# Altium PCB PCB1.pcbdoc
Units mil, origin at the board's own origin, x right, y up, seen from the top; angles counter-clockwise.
Board outline 1870.1 x 2920.8 mil, 2 copper layers (Top Layer, Bottom Layer), stack 62.2 mil thick; 51 components, 45 nets, 147 pads, 92 vias.
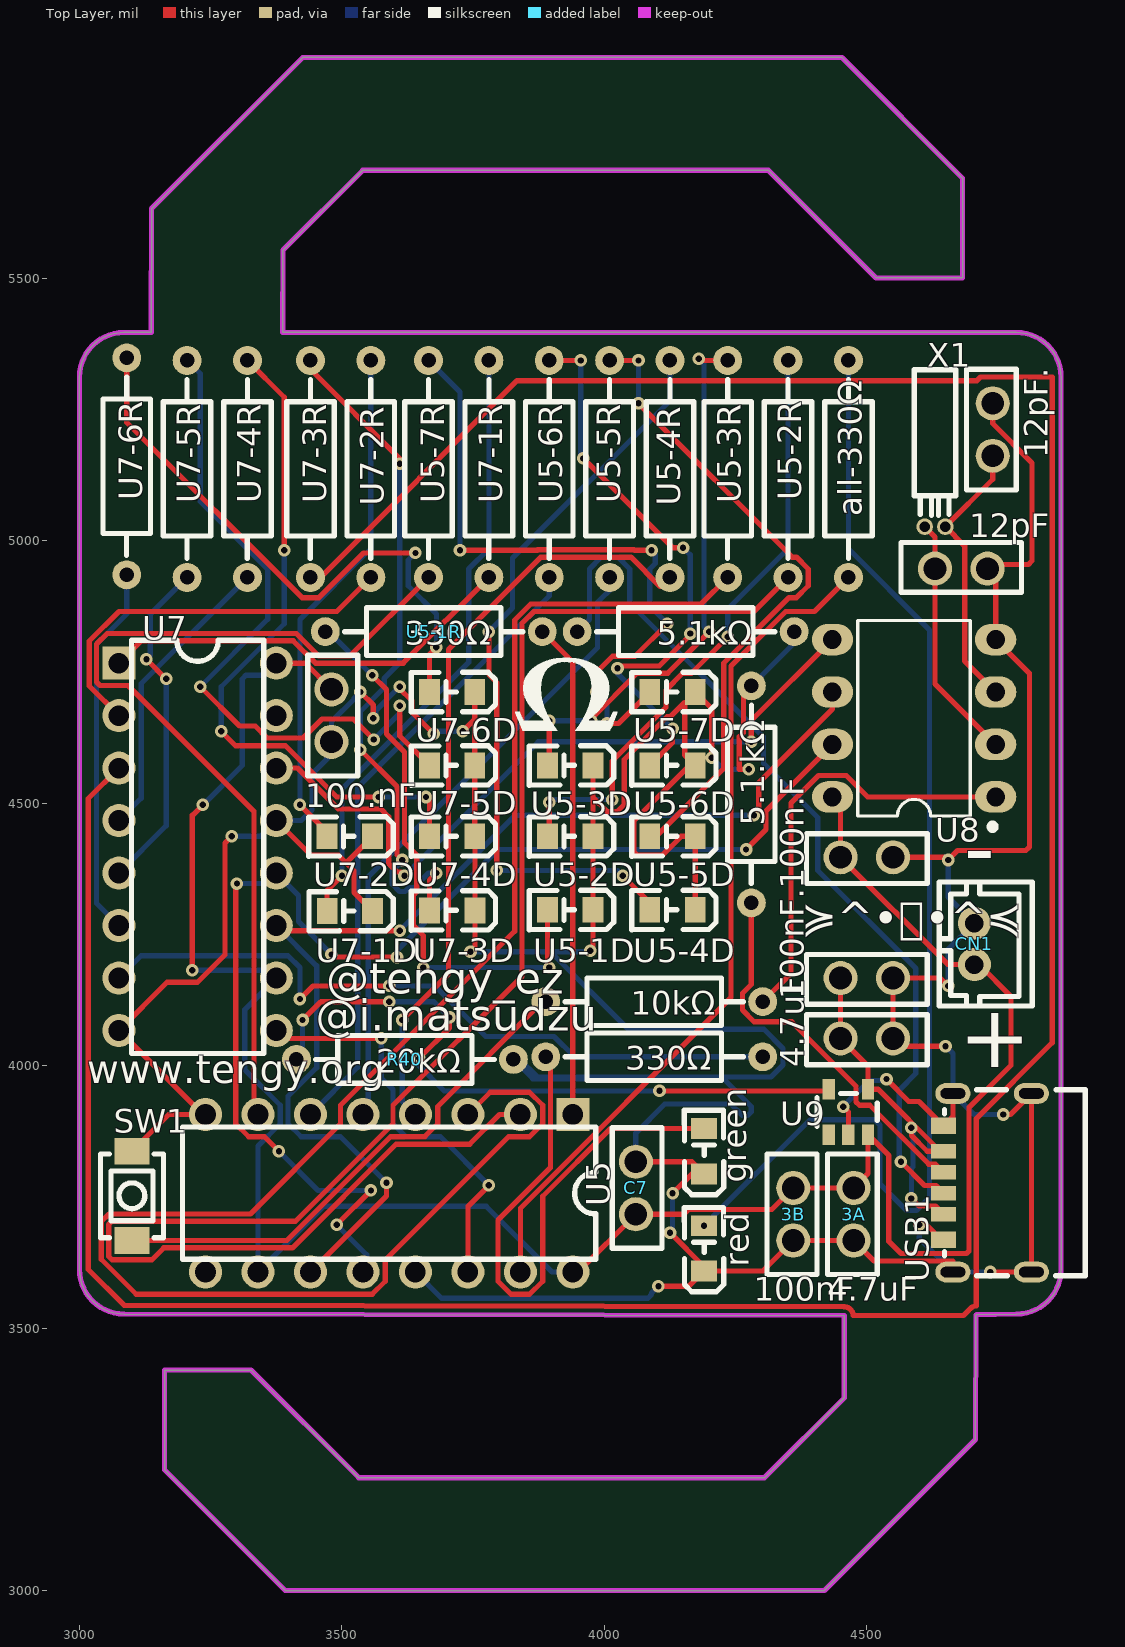
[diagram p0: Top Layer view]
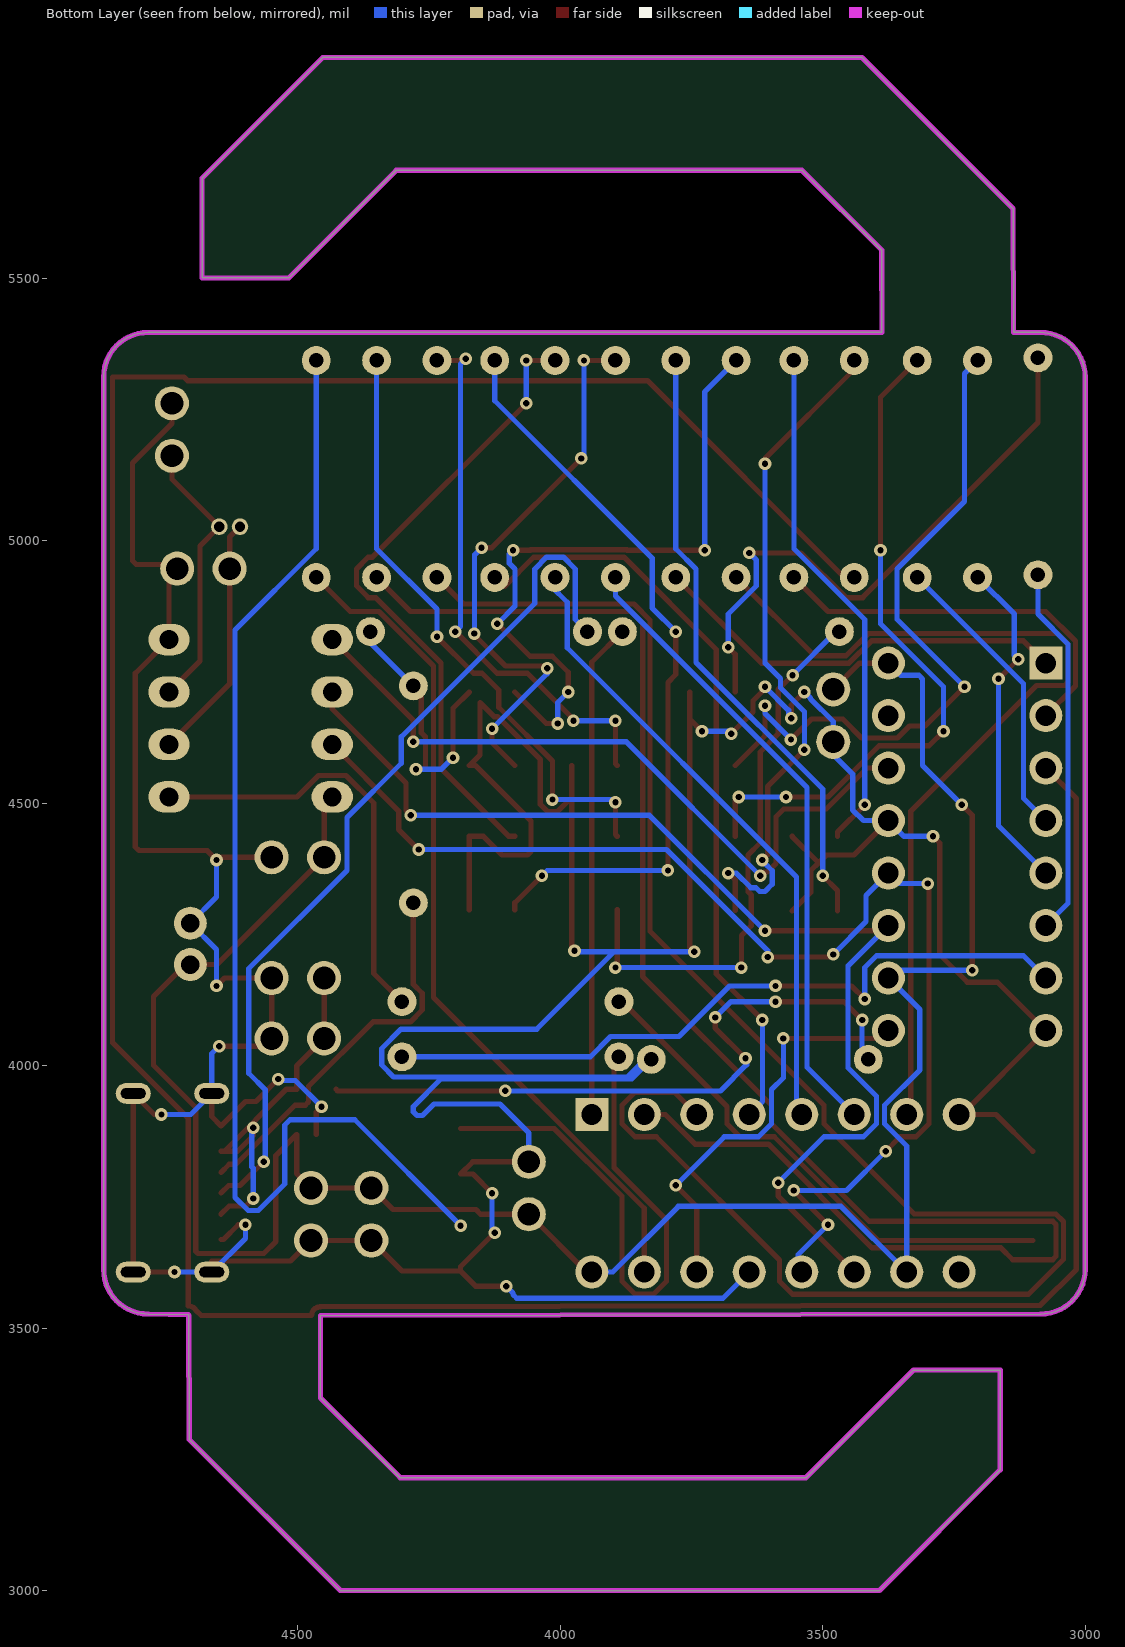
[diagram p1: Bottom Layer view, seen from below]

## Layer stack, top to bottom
Top Solder Mask Layer: solder mask 0.4, Dk 3.3
Top Layer: signal copper 1.4
Dielectric1: surface 59.4, FR4, Dk 4.5
Bottom Layer: signal copper 1.4
Bottom Solder Mask Layer: solder mask 0.4, Dk 3.3

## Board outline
4785.1,3526.8 4709,3525.4 4708,3523.8 4707,3287.9 4419.1,3000 3392,3000 3162,3230 3162,3420 3327,3420 3532,3215 4304.9,3215 4457,3367.1 4457.1,3523.8 3085,3526.8 cw(c3085,3611.8) 3000,3611.8 3000,5311.9 cw(c3085,5311.9) 3085,5396.9 3084.7,5396.9 3136.5,5396.9 3137.4,5632.8 3425.4,5920.8 4452.5,5920.8 4682.5,5690.8 4682.5,5500.8 4517.5,5500.8 4312.5,5705.8 3539.6,5705.8 3387.5,5553.7 3387.3,5396.9 4785.1,5396.9 cw(c4785.1,5311.9) 4870.1,5311.9 4870.1,3611.8 cw(c4785.1,3611.8)

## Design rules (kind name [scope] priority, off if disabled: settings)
BoardOutlineClearance copperThickness1oz [All] p0: genericclearance=10 ignorepadtopadclearanceinfootprint=FALSE except(0: Arc-SplitContinuation Track-SplitContinuation SMDPad-SplitContinuation THPad-SplitContinuation Via-SplitContinuation Fill-SplitContinuation Poly-SplitContinuation Region-SplitContinuation Text-SplitContinuation)
BoardOutlineClearance copperThickness2oz [All] p0: genericclearance=10 ignorepadtopadclearanceinfootprint=FALSE except(0: Arc-SplitContinuation Track-SplitContinuation SMDPad-SplitContinuation THPad-SplitContinuation Via-SplitContinuation Fill-SplitContinuation Poly-SplitContinuation Region-SplitContinuation Text-SplitContinuation)
BoardOutlineClearance Plane_innerPlane [All] p0: genericclearance=10 ignorepadtopadclearanceinfootprint=FALSE except(0: Arc-SplitContinuation Track-SplitContinuation SMDPad-SplitContinuation THPad-SplitContinuation Via-SplitContinuation Fill-SplitContinuation Poly-SplitContinuation Region-SplitContinuation Text-SplitContinuation)
BoardOutlineClearance Copper_copperRegion [All] p0: genericclearance=10 ignorepadtopadclearanceinfootprint=FALSE except(0: Arc-SplitContinuation Track-SplitContinuation SMDPad-SplitContinuation THPad-SplitContinuation Via-SplitContinuation Fill-SplitContinuation Poly-SplitContinuation Region-SplitContinuation Text-SplitContinuation)
BoardOutlineClearance otherClearance [All] p0: genericclearance=10 ignorepadtopadclearanceinfootprint=FALSE except(0: Arc-SplitContinuation Track-SplitContinuation SMDPad-SplitContinuation THPad-SplitContinuation Via-SplitContinuation Fill-SplitContinuation Poly-SplitContinuation Region-SplitContinuation Text-SplitContinuation)
Clearance copperThickness1oz [All] p1: gap=7 ignorepadtopadclearanceinfootprint=FALSE
Clearance copperThickness2oz [All] p1: gap=7 ignorepadtopadclearanceinfootprint=FALSE
Clearance Plane_innerPlane [All] p1: gap=7 ignorepadtopadclearanceinfootprint=FALSE
Clearance Copper_copperRegion [All] p1: gap=7 ignorepadtopadclearanceinfootprint=FALSE
Clearance otherClearance [All] p1: gap=7 ignorepadtopadclearanceinfootprint=FALSE
DiffPairsRouting differentialPair [All] p1: maxuncoupledlength=10 minlimit=6 maxlimit=Infinity mostfreqgap=6 toplayer_minwidth=5 toplayer_prefwidth=10 toplayer_maxwidth=100 bottomlayer_minwidth=5 bottomlayer_prefwidth=10 bottomlayer_maxwidth=100
PasteMaskExpansion pasteMaskExpansion [All] p1: expansion=0
PlaneConnect innerPlane [All] p1: planeconnectstyle=Relief reliefexpansion=20 reliefentries=4 reliefconductorwidth=10 reliefairgap=10
PolygonConnect copperRegion [All] p1: connectstyle=Relief reliefentries=4 reliefconductorwidth=10 polygonreliefangle="90 Angle" airgapwidth=10
RoutingVias viaSize [All] p1: viastyle="Through Hole" holewidth=12.0078 minholewidth=11.811 maxholewidth=248.0314 width=12.0078 minwidth=11.811 maxwidth=248.0314
SolderMaskExpansion solderMaskExpansion [IsVia] p1: useseparateexpansions=TRUE expansion=-1000 expansionbottom=-1000
SolderMaskExpansion solderMaskExpansion [All] p2: useseparateexpansions=TRUE expansion=2 expansionbottom=2
Width copperThickness1oz [All] p1: maxlimit=100 minlimit=5 preferedwidth=10
Width copperThickness2oz [All] p1: maxlimit=100 minlimit=8 preferedwidth=10

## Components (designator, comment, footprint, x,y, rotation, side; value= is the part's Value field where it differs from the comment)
3A "4.7uF" CAP-TH_L5.8-W2.4-P2.54-D0.6 4475,3716.9 r270 top
3B "100nF" CAP-TH_L5.8-W2.4-P2.54-D0.6 4360,3716.9 r270 top
4.7uF "100nF" CAP-TH_L5.8-W2.4-P2.54-D0.6 4500,4051.9 r0 top
5.1.kΩ "1kΩ" RES-TH_BD2.3-L6.5-P10.50-D0.5 4280,4516.9 r90 top
5.1kΩ "1kΩ" RES-TH_BD2.3-L6.5-P10.50-D0.5 4155,4826.9 r0 top
10kΩ "1kΩ" RES-TH_BD2.3-L6.5-P10.50-D0.5 4095,4121.9 r0 top
12pF "100nF" CAP-TH_L5.8-W2.4-P2.54-D0.6 4680,4946.9 r180 top
12pF. "100nF" CAP-TH_L5.8-W2.4-P2.54-D0.6 4740,5211.9 r270 top
100.nF "100nF" CAP-TH_L5.8-W2.4-P2.54-D0.6 3480,4666.9 r90 top
100n.F "100nF" CAP-TH_L5.8-W2.4-P2.54-D0.6 4500,4396.9 r0 top
100nF. "100nF" CAP-TH_L5.8-W2.4-P2.54-D0.6 4500,4166.9 r0 top
330Ω "1kΩ" RES-TH_BD2.3-L6.5-P10.50-D0.5 4095,4016.9 r0 top
all-330Ω "1kΩ" RES-TH_BD2.3-L6.5-P10.50-D0.5 4465,5136.9 r90 top
C7 "100nF" CAP-TH_L5.8-W2.4-P2.54-D0.6 4060,3766.9 r90 top
CN1 "B2B-PH-K-S-GW" CONN-TH_B2B-PH-K-S 4705,4231.9 r270 top
green "TJ-S2012EX8T5ALC2R-A5" LED0805-RD 4190,3836.9 r90 top
R40 "20kΩ" RES-TH_BD2.3-L6.5-P10.50-D0.5 3620,4011.9 r0 top
red "TJ-S2012EX8T5ALC2R-A5" LED0805-RD 4190,3651.9 r90 top
SW1 "HX 3x4x2-2P-1.6N TACTILE SWITCH" KEY-SMD_L4.0-W3.0-LS4.9-1 3100,3751.9 r270 top
U5 "74HC595N" DIP-16_L19.8-W6.5-P2.54-LS7.6-BL 3590,3756.9 r180 top
U5-1D "TJ-S2012EX8T5ALC2R-A5" LED0805-RD 3935,4296.9 r180 top
U5-1R "330Ω" RES-TH_BD2.3-L6.5-P10.50-D0.5 3675,4826.9 r0 top
U5-2D "TJ-S2012EX8T5ALC2R-A5" LED0805-RD 3935,4436.9 r180 top
U5-2R "1kΩ" RES-TH_BD2.3-L6.5-P10.50-D0.5 4350,5136.9 r270 top
U5-3D "TJ-S2012EX8T5ALC2R-A5" LED0805-RD 3935,4571.9 r180 top
U5-3R "1kΩ" RES-TH_BD2.3-L6.5-P10.50-D0.5 4235,5136.9 r270 top
U5-4D "TJ-S2012EX8T5ALC2R-A5" LED0805-RD 4130,4296.9 r180 top
U5-4R "1kΩ" RES-TH_BD2.3-L6.5-P10.50-D0.5 4125,5136.9 r270 top
U5-5D "TJ-S2012EX8T5ALC2R-A5" LED0805-RD 4130,4436.9 r180 top
U5-5R "1kΩ" RES-TH_BD2.3-L6.5-P10.50-D0.5 4010,5136.9 r270 top
U5-6D "TJ-S2012EX8T5ALC2R-A5" LED0805-RD 4130,4571.9 r180 top
U5-6R "1kΩ" RES-TH_BD2.3-L6.5-P10.50-D0.5 3895,5136.9 r270 top
U5-7D "TJ-S2012EX8T5ALC2R-A5" LED0805-RD 4130,4711.9 r180 top
U5-7R "1kΩ" RES-TH_BD2.3-L6.5-P10.50-D0.5 3665,5136.9 r270 top
U7 "74HC595N" DIP-16_L19.8-W6.5-P2.54-LS7.6-BL 3225,4416.9 r270 top
U7-1D "TJ-S2012EX8T5ALC2R-A5" LED0805-RD 3515.1,4294.5 r180 top
U7-1R "1kΩ" RES-TH_BD2.3-L6.5-P10.50-D0.5 3780,5136.9 r270 top
U7-2D "TJ-S2012EX8T5ALC2R-A5" LED0805-RD 3515,4436.9 r180 top
U7-2R "1kΩ" RES-TH_BD2.3-L6.5-P10.50-D0.5 3555,5136.9 r270 top
U7-3D "TJ-S2012EX8T5ALC2R-A5" LED0805-RD 3710.1,4295.9 r180 top
U7-3R "1kΩ" RES-TH_BD2.3-L6.5-P10.50-D0.5 3440,5136.9 r270 top
U7-4D "TJ-S2012EX8T5ALC2R-A5" LED0805-RD 3710,4436.9 r180 top
U7-4R "1kΩ" RES-TH_BD2.3-L6.5-P10.50-D0.5 3320,5136.9 r270 top
U7-5D "TJ-S2012EX8T5ALC2R-A5" LED0805-RD 3710,4571.9 r180 top
U7-5R "1kΩ" RES-TH_BD2.3-L6.5-P10.50-D0.5 3205,5136.9 r270 top
U7-6D "TJ-S2012EX8T5ALC2R-A5" LED0805-RD 3710,4711.9 r180 top
U7-6R "1kΩ" RES-TH_BD2.3-L6.5-P10.50-D0.5 3090,5141.9 r270 top
U8 "ATTINY85-20PU" PDIP-8_L9.3-W6.4-P2.54-LS7.9-BL-1 4590,4661.9 r90 top
U9 "MCP73831T-2DCI/OT" SOT-23-5_L2.9-W1.6-P0.95-LS2.8-BL 4465,3911.9 r0 top
USB1 "TYPE-C 6P(073)" TYPE-C-SMD_TYPE-C-6P-073 4730,3776.9 r90 top
X1 "32.768kHz" OSC-TH_BD2.0-P0.70-D0.3 4630,5026.9 r270 top

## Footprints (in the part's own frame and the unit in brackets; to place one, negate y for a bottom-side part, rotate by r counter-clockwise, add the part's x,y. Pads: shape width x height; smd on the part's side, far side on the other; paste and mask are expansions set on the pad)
CAP-TH_L5.8-W2.4-P2.54-D0.6 [mil]
  round 65 hole 43.3 paste+0 mask+2: 1(-50,0) 2(50,0)
  silkscreen extent -115,-50 115,45
CONN-TH_B2B-PH-K-S [mil]
  round 63 hole 35.4: 1(39.3,0) 2(-39.4,0)
  silkscreen extent -118,-67 118,110
DIP-16_L19.8-W6.5-P2.54-LS7.6-BL [mil]
  rect 63x63 hole 39.4: 1(-350,-150)
  round 63 hole 39.4: 2(-250,-150) 3(-150,-150) 4(-50,-150) 5(50,-150) 6(150,-150) 7(250,-150) 8(350,-150) 9(350,150) 10(250,150) 11(150,150) 12(50,150) 13(-50,150) 14(-150,150) 15(-250,150) 16(-350,150)
  silkscreen extent -394,-126 394,126
KEY-SMD_L4.0-W3.0-LS4.9-1 [mil]
  rect 51.2x66.9 smd paste+0 mask+2: 1(-85,0) 2(85,0)
  silkscreen extent -80,-60 80,60
LED0805-RD [mil]
  rect 39.4x49.2 smd: 1(-43.3,0) 2(43.3,0)
  silkscreen extent -83,-37 78,38
OSC-TH_BD2.0-P0.70-D0.3 [mil]
  round 31.5 hole 19.7: 1(0,19.7) 2(0,-19.7)
  silkscreen extent -299,-39 -21,39
PDIP-8_L9.3-W6.4-P2.54-LS7.9-BL-1 [mil]
  oval 60x78.7 hole 35.4: 1(-150,-155.5) 2(-50,-155.5) 3(50,-155.5) 4(150,-155.5) 5(150,155.5) 6(50,155.5) 7(-50,155.5) 8(-150,155.5)
  silkscreen extent -213,-156 186,107
RES-TH_BD2.3-L6.5-P10.50-D0.5 [mil]
  round 55.1 hole 27.6: 1(-206.7,0) 2(206.7,0)
  silkscreen extent -170,-45 170,45
SOT-23-5_L2.9-W1.6-P0.95-LS2.8-BL [mil]
  rect 23.6x39.4 smd paste+0 mask+2: 1(-37.4,-43.3) 2(0,-43.3) 3(37.4,-43.3) 4(37.4,43.3) 5(-37.4,43.3)
  silkscreen extent -60,-28 55,35
TYPE-C-SMD_TYPE-C-6P-073 [mil]
  oval 39.4x66.9 hole 19.7 slot 47.2 at 90 deg: 7(-170.1,-83.7) 7(-170.1,65.9) 7(170.1,-83.7) 7(170.1,65.9)
  rect 27.6x47.2 smd paste-3937 mask+2: A5(-19.7,83.7) A9(59.9,83.7) B5(19.7,83.7) B9(-59.8,83.7)
  rect 31.5x47.2 smd paste-3937 mask+2: A12(108.3,83.7) B12(-108.2,83.7)
  silkscreen extent -177,-186 177,82

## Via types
v1: diameter 24, hole 12, Top Layer to Bottom Layer, 92 vias

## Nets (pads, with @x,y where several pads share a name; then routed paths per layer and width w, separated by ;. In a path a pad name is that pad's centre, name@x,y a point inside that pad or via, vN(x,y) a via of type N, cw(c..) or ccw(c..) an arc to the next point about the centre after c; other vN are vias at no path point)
$1N1454: U7.14 U8.5 | length 1406.6
  Top Layer w10: U7.14 3415.3,4566.9 3493.2,4488.9 3574.2,4488.9 3589,4474.2 3589,4385.4 3605.5,4368.9 3612.1,4368.9 v1(3619.1,4361.9) ; v1(4280,4616.9) 4280,4657.4 U8.5
  Bottom Layer w10: v1(3619.1,4361.9) 3874.1,4616.9 v1(4280,4616.9)
$1N1740: U5.14 U7.9 | length 790.8
  Top Layer w10: U7.9 3390,4051.9 v1(3575,4051.9) ; U5.14 3740,3731.9 v1(3780,3771.9)
  Bottom Layer w10: v1(3575,4051.9) 3575,3976.9 3597.5,3954.4 3597.5,3889.3 3622.4,3864.4 3687.5,3864.4 v1(3780,3771.9)
$1N3175: U5-5D.2 U5-5R.1 | length 1240.3
  Top Layer w10: U5-5R.1 v1(4065,5343.6) ; v1(4065,5261.9) 4358.1,4968.8 4366,4968.8 4388.5,4946.2 4388.5,4914.3 4366,4891.7 4351.8,4891.7 4227.4,4767.3 4227.4,4566.2 4098.1,4436.9 U5-5D.2
  Bottom Layer w10: v1(4065,5261.9) v1(4065,5343.6)
$1N3221: U5-4D.2 U5-4R.1 | length 1451.4
  Top Layer w10: v1(3780,4826.9) 3780,4745.1 3795,4730.1 v1(3795,4371.9) ; v1(4035,4361.9) 4086.7,4310.2 U5-4D.2
  Bottom Layer w10: v1(3780,4826.9) 3825,4871.9 3825,4966.9 4125,5266.9 U5-4R.1 ; v1(3795,4371.9) 4025,4371.9 v1(4035,4361.9)
$1N3267: U5-3D.2 U5-3R.1 | length 1048.3
  Top Layer w10: U5-3D.2 3895,4575.2 v1(3895,4656.9) ; v1(3975,4656.9) 3975,4660.1 4062.5,4747.5 4120.6,4747.5 v1(4200,4826.9) ; v1(4180,5346.9) 4183.3,5343.6 U5-3R.1
  Bottom Layer w10: v1(3895,4656.9) v1(3975,4656.9) ; v1(4180,5346.9) 4190,5336.9 4190,4836.9 v1(4200,4826.9)
$1N3313: U5-2D.2 U5-2R.1 | length 1173.6
  Top Layer w10: U5-2D.2 3895,4440.2 v1(3895,4501.9) ; v1(4015,4506.9) 4015,4580.4 4117.4,4682.8 4117.4,4715.8 4149.1,4747.5 4165.6,4747.5 v1(4235,4816.9)
  Bottom Layer w10: v1(3895,4501.9) 3900,4506.9 v1(4015,4506.9) ; v1(4235,4816.9) 4235,4869.7 4350,4984.7 U5-2R.1
$1N3359: U5-1D.2 U5-1R.1 | length 1077.6
  Top Layer w10: v1(3557.5,4743.9) 3585,4716.4 3585,4631.7 3619,4597.7 3619,4424.8 3642.5,4401.2 3642.5,4331.5 3636.1,4325 3636.1,4266.7 3655,4247.8 v1(3655,4186.9) ; U5-1D.2 3891.7,4190.2 v1(3895,4186.9)
  Bottom Layer w10: U5-1R.1 3474.5,4826.9 v1(3557.5,4743.9) ; v1(3655,4186.9) v1(3895,4186.9)
$1N7289: U7-1D.2 U7-1R.1 | length 1176.8
  Top Layer w10: U7-1D.2 3471.8,4333.7 v1(3500,4361.9)
  Bottom Layer w10: v1(3500,4361.9) 3500,4526.9 3741.5,4768.4 3741.5,4946.2 3780,4984.7 U7-1R.1
$1N7335: U7-2D.2 U7-2R.1 | length 984
  Top Layer w10: v1(3420,4496.9) 3471.7,4445.2 U7-2D.2
  Bottom Layer w10: v1(3420,4496.9) 3420,4849.7 3555,4984.7 U7-2R.1
$1N7381: U7-3D.2 U7-3R.1 | length 1320.9
  Top Layer w10: U7-3R.1 3440,5326.9 3610,5156.9 v1(3610,5146.9) ; v1(3535,4601.9) 3605,4531.9 3605,4401.9 v1(3615,4391.9) ; U7-3D.2 3666.8,4353.7 v1(3680,4366.9)
  Bottom Layer w10: v1(3535,4601.9) 3535,4674.4 3580.5,4719.9 3580.5,4737.4 3610,4766.9 v1(3610,5146.9) ; v1(3615,4391.9) 3610,4386.9 3610,4385.3 3596.1,4371.4 3596.1,4345.8 3610,4331.9 3620,4331.9 3627,4338.9 3637,4338.9 3665,4366.9 v1(3680,4366.9)
$1N7427: U7-4D.2 U7-4R.1 | length 1305
  Top Layer w10: v1(3270,4636.9) 3297.5,4609.4 3392.6,4609.4 3490.1,4511.9 v1(3570,4511.9) ; U7-4R.1 3390,5273.6 v1(3390,4981.9) ; v1(3660,4511.9) 3666.7,4505.2 U7-4D.2
  Bottom Layer w10: v1(3270,4636.9) 3270,4722 3390,4842 v1(3390,4981.9) ; v1(3570,4511.9) v1(3660,4511.9)
$1N7473: U7-5D.2 U7-5R.1 | length 1362.7
  Top Layer w10: v1(3230,4721.9) 3305,4646.9 3334.9,4646.9 3357.4,4624.4 3426.1,4624.4 3462,4660.4 3521.5,4660.4 v1(3560.6,4621.3) ; v1(3610,4685.7) 3610,4628.6 U7-5D.2
  Bottom Layer w10: U7-5R.1 3230,5318.6 3230,5074.7 3358.5,4946.2 3358.5,4850.5 v1(3230,4721.9) ; v1(3560.6,4621.3) 3610,4670.7 v1(3610,4685.7)
$1N7519: U7-6D.2 U7-6R.1 | length 1144.8
  Top Layer w10: U7-6R.1 3090,5225.7 3424,4891.7 3456,4891.7 3541.2,4976.9 v1(3640,4976.9) ; U7-6D.2 3666.7,4783.6 v1(3680,4796.9)
  Bottom Layer w10: v1(3640,4976.9) 3626.5,4963.4 3626.5,4914.3 3680,4860.7 v1(3680,4796.9)
$1N7565: 330Ω.1 green.2 | length 1101.2
  Top Layer w10: 330Ω.1 3897.5,4007.7 3897.5,3805.7 3797.5,3705.7 3797.5,3589.3 3822.4,3564.4 3857.6,3564.4 3882.5,3589.3 3882.5,3751.1 4011.7,3880.2 green.2
$1N8990: U5-6D.2 U5-6R.1 | length 1091.9
  Top Layer w10: U5-6R.1 v1(3955,5343.6) ; v1(3960,5156.9) 4130,4986.9 v1(4150,4986.9) ; v1(4025,4756.9) 4029.6,4761.5 4104.6,4761.5 v1@4165,4821.9 ; U5-6D.2 4130,4615.2 v1(4130,4641.9)
  Bottom Layer w10: v1(3955,5343.6) 3955,5161.9 v1(3960,5156.9) ; v1(4025,4756.9) 4025,4746.9 v1(4130,4641.9) ; v1(4150,4986.9) 4163.7,4973.2 v1(4163.7,4823.2)
$1N8994: U5-7D.2 U5-7R.1 | length 1299.2
  Top Layer w10: v1(3725,4981.9) 3872.4,4981.9 3873.2,4982.8 4056.4,4982.8 4057.3,4981.9 v1(4090,4981.9) ; v1(3985,4711.9) 3985,4749.4 4015.5,4779.9 4058,4779.9 v1(4120,4841.9) ; v1(4005,4651.9) 4026.7,4651.9 U5-7D.2
  Bottom Layer w10: U5-7R.1 3725,5283.6 v1(3725,4981.9) ; v1(3985,4711.9) 4005,4691.9 v1(4005,4651.9) ; v1(4090,4981.9) 4097.1,4974.8 4097.1,4956.8 4086.5,4946.2 4086.5,4875.5 v1(4120,4841.9)
$1N10884: all-330Ω.1 U5.15 | length 1614.1
  Top Layer w10: U5.15 3840,3728.4 4241.5,4129.9 4241.5,4761.2 4345.7,4865.5 4400.2,4865.5 all-330Ω.1
$1N10886: all-330Ω.2 red.2 | length 2319.7
  Bottom Layer w10: v1(4190,3695.2) 4391.7,3896.9 4515,3896.9 4525,3886.9 4525,3774.4 4575.5,3723.9 4594.5,3723.9 4619.6,3749 4619.6,4830.1 4465,4984.7 all-330Ω.2
$1N10962: 10kΩ.2 U8.1 | length 829.5
  Top Layer w10: 10kΩ.2 4355.5,4175.7 4355.5,4500.3 4408.1,4552.9 4460.8,4552.9 4501.8,4511.9 U8.1
$1N10964: 10kΩ.1 SW1.2 | length 996
  Top Layer w10: SW1.2 3394.9,3666.9 3592.5,3864.4 3657.6,3864.4 3682.5,3889.3 3682.5,3922.2 3882.2,4121.9 10kΩ.1
$1N11563: U5-1R.2 U5.1 | length 944.1
  Top Layer w10: U5-1R.2 3940,4768.6 U5.1
$1N11565: U5-2R.2 U5.2 | length 3181.9
  Top Layer w10: U5.2 3800.1,3906.9 3743.6,3850.4 3603.5,3850.4 3406,3652.9 3160.6,3652.9 3138,3630.3 3062,3630.3 3055.6,3636.8 3055.6,3697.1 3062,3703.5 3411.7,3703.5 3597.5,3889.3 3597.5,3924.5 3843.1,4170.1 3843.1,4842.9 3865.7,4865.5 4285.2,4865.5 U5-2R.2
$1N11567: U5-3R.2 U5.3 | length 3373.9
  Top Layer w10: U5.3 3782.5,3949.4 3857.6,3949.4 3882.5,3924.5 3882.5,3889.3 3857.6,3864.4 3817.3,3864.4 3582.5,3629.6 3582.5,3589.3 3557.6,3564.4 3108.1,3564.4 3041.5,3631 3041.5,3702.9 3056.2,3717.5 3325.7,3717.5 3497.5,3889.3 3497.5,3924.5 3829.1,4256.1 3829.1,4848.7 3859.9,4879.5 4184.2,4879.5 U5-3R.2
$1N11569: U5-4R.2 U5.4 | length 1477.7
  Top Layer w10: v1(3615,4086.9) 3703,4174.9 3703,4792.7 3879,4968.8 4050.6,4968.8 4106.2,4913.2 4132.1,4913.2 4132.1,4923.2 U5-4R.2
  Bottom Layer w10: v1(3615,4086.9) 3615,3931.9 U5.4
$1N11571: U5-5R.2 U5.5 | length 1223.9
  Bottom Layer w10: U5.5 3550,3916.9 3550,4359.4 3986.9,4796.3 3986.9,4882.9 4017.1,4913.2 4017.1,4923.2 U5-5R.2
$1N11573: U5-6R.2 U5.6 | length 1211.8
  Bottom Layer w10: U5.6 3530,3996.9 3530,4529.7 3895,4894.7 U5-6R.2
$1N11575: U5-7R.2 U5.7 | length 1775.2
  Top Layer w10: U5.7 3332.5,3914.4 3332.5,4484.5 3092.6,4724.4 3039,4724.4 3032.5,4730.9 3032.5,4803 3053,4823.4 3413.1,4823.4 3455.6,4780.9 3515.7,4780.9 U5-7R.2
$1N11659: U7-1R.2 U7.1 | length 807.8
  Top Layer w10: U7.1 3117.5,4809.4 3407.3,4809.4 3449.8,4766.9 3616.7,4766.9 U7-1R.2
$1N11661: U7-2R.2 U7.2 | length 752.1
  Top Layer w10: U7.2 3018.5,4723.4 3018.5,4808.8 3075.2,4865.5 3490.2,4865.5 U7-2R.2
$1N11663: U7-3R.2 U7.3 | length 6117
  Top Layer w10: U7.3 3016.8,4508.7 3016.8,3611.8 3085,3543.7 4457.2,3540.7 ; U7-3R.2 3459,4930.2 3833.9,5305.1 4710,5305.1 4716.9,5311.9 4853.3,5311.9 4853.3,4043.8 4708.7,3899.2 4708.7,3542.2 ccw(c4709,3525.4) 4694.91,3534.55 ; 4457.13,3540.6 cw(c4457.1,3523.8) 4473.9,3523.77 ; 4473.9,3523.8 4684.2,3523.8 4694.9,3534.6
$1N11665: U7-4R.2 U7.4 | length 564.8
  Bottom Layer w10: U7.4 3117.5,4509.4 3117.5,4727.7 U7-4R.2
$1N11667: U7-5R.2 U7.5 | length 648.3
  Top Layer w10: v1(3127.5,4774.4) v1(3165.1,4736.9)
  Bottom Layer w10: U7.5 3165.1,4457 v1(3165.1,4736.9) ; v1(3127.5,4774.4) 3135,4781.9 3135,4860.2 U7-5R.2
$1N11669: U7-6R.2 U7.6 | length 709.8
  Bottom Layer w10: U7.6 3032.5,4309.4 3032.5,4803 3090,4860.4 U7-6R.2
$1N11671: 330Ω.2 U7.7 | length 1379.9
  Top Layer w10: v1(3420,4126.9) 3445,4151.9 v1(3590,4151.9)
  Bottom Layer w10: U7.7 3117.5,4209.4 3397.5,4209.4 3420,4186.9 v1(3420,4126.9) ; v1(3590,4151.9) 3677.5,4151.9 3774,4055.5 3904.3,4055.5 3942.8,4016.9 330Ω.2
$1N11673: U7.15
$1N13466: 12pF.2 U8.2 X1.2 | length 471
  Top Layer w10: X1.2 4630,5007.2 12pF.2 4630,4727.4 U8.2
$1N13478: 12pF..2 U8.3 X1.1 | length 527.1
  Top Layer w10: 12pF..2 4740,5117.2 X1.1 4686.5,4990.1 4686.5,4770.9 U8.3
$1N15286: 4.7uF.1 100nF..1 U9.4 USB1.A9 USB1.B9 | length 719.8
  Top Layer w10: 100nF..1 4.7uF.1 4502.4,3999.5 U9.4 4521.4,3955.2 USB1.A9@4639.9,3836.8 ; v1(4585,3746.9) 4599.4,3732.5 4630.9,3732.5 USB1.B9 ; v1(4585,3881.9) 4585,3866.9 4615.2,3836.8 USB1.A9@4639.9,3836.8 ; USB1.A9 USB1.A9@4639.9,3836.8
  Bottom Layer w10: v1(4585,3746.9) 4585,3804.4 4588,3807.4 4588,3878.9 v1(4585,3881.9)
$1N15518: R40.1 U9.5 | length 1306.3
  Top Layer w10: v1(3425,4086.9) 3460,4121.9 v1(3590,4121.9) ; v1(3647.1,4014) 3705,4071.9 v1(3705,4091.9) ; v1(4105,3951.9) 4424.3,3951.9 U9.5
  Bottom Layer w10: R40.1 3425,4023.6 v1(3425,4086.9) ; v1(3590,4121.9) 3675,4121.9 v1(3705,4091.9) ; v1(3647.1,4014) 3645,4011.9 3645,4001.9 3695,3951.9 v1(4105,3951.9)
$1N16011: 5.1.kΩ.1 USB1.B5 | length 740.1
  Top Layer w10: 5.1.kΩ.1 4280,4154.7 4263.1,4137.9 4263.1,4106 4285.7,4083.4 4357.1,4083.4 4479.6,3960.8 4479.6,3931 4486,3924.6 4505.6,3924.6 4618.2,3812 4630.9,3812 USB1.B5
$1N16013: 5.1kΩ.1 USB1.A5 | length 1700
  Top Layer w10: v1(4565,3816.9) 4610.1,3771.8 4631.7,3771.8 USB1.A5
  Bottom Layer w10: 5.1kΩ.1 3971.5,4850.1 3971.5,4946.2 3994,4968.8 4026,4968.8 4048.5,4946.2 4048.5,4880.9 4303,4626.4 4303,4576.1 4406.5,4472.5 4406.5,4371.9 4593.5,4184.9 4593.5,3985.4 4562,3953.9 4562,3819.9 v1(4565,3816.9)
GND: 3A.2 3B.2 4.7uF.2 5.1.kΩ.2 5.1kΩ.2 12pF.1 12pF..1 100.nF.1 100n.F.2 100nF..2 C7.2 CN1.2 green.1 R40.2 red.1 SW1.1 U5-1D.1 U5-2D.1 U5-3D.1 U5-4D.1 U5-5D.1 U5-6D.1 U5-7D.1 U5.8 U5.13 U7-1D.1 U7-2D.1 U7-3D.1 U7-4D.1 U7-5D.1 U7-6D.1 U7.8 U7.13 U8.4 U9.2 USB1.7 USB1.A12 USB1.B12 | length 11207.6
  Top Layer w10: SW1.1 3170,3906.9 U5.8@3235,3906.9 ; U5.8 U5.8@3235,3906.9 ; v1(3290,4436.9) 3277,4423.9 3277,4211.4 3224.5,4158.9 3167,4158.9 U7.8 U5.8@3235,3906.9 ; U7.13 3440.6,4401.3 3493.1,4401.3 3507.3,4387.2 ; v1(3535,4711.9) 3559.9,4687 v1(3559.9,4661.9) ; U7-2D.1 3508.6,4387.2 3507.3,4387.2 ; U7-1D.1 3523,4329.9 3523,4371.4 3507.3,4387.2 ; v1(3610,4721.9) 3610,4718.2 3633,4695.2 3633,4673.9 v1(3674.6,4632.3) ; v1(3730,4636.9) 3753.3,4660.2 ; v1(3745,4216.9) 3753.4,4225.3 U7-3D.1 3753.4,4436.8 U7-4D.1 U7-5D.1 3753.3,4660.2 ; U7-6D.1 3753.3,4660.2 ; v1(3972.9,4219) 3978.3,4224.4 U5-1D.1 U5-2D.1 3978.3,4511.1 ; U5-3D.1 3978.3,4511.1 ; C7.2 4166.7,3816.9 green.1 4166.7,3793.6 v1(4130,3756.9) ; v1(4103,3579.9) 4161.3,3579.9 red.1 ; v1(4125,3681.9) 4190,3616.9 red.1 ; U5-4D.1 U5-5D.1 4146.5,4436.9 4110.9,4401.3 4062.5,4401.3 4056,4407.8 4056,4466.1 4161.9,4571.9 U5-6D.1 4153,4592.2 4153,4691.6 4126.3,4664.9 4119.9,4664.9 4038,4583 4038,4497.4 4024.5,4483.9 4005.5,4483.9 3978.3,4511.1 ; U5-7D.1 4204.4,4680.8 v1(4204.4,4586.9) ; v1(4275,4564.9) 4257,4564.9 4257,4626.4 4265,4634.4 4265,4708.6 5.1.kΩ.2 ; v1(4455,3921.9) 4465,3911.9 U9.2 ; v1(4537.5,3974.4) 4580,3931.9 4599.6,3931.9 USB1.A12 4664.1,3902.9 USB1.7@4664.1,3947 ; 100n.F.2 4650,4396.9 v1(4655,4391.9) 4672.9,4409.8 4802.9,4409.8 4810,4416.9 4810,4747.4 U8.4 4745.5,4931.4 12pF.1 4737.9,4954.8 4807.9,4954.8 4815,4961.9 4815,5148.4 4740,5223.4 12pF..1 ; v1(4600,3696.9) 4613.6,3696.9 4641.8,3668.7 USB1.B12 ; v1(4650,4036.9) 4565,4036.9 4.7uF.2 100nF..2 4640,4166.9 v1(4655,4151.9) ; USB1.7@4664.1,3606.8 4664.1,3627.9 4514,3627.9 3A.2 3B.2 4301.7,3608.6 red.1 ; v1(4735,3606.8) 4813.7,3606.8 4813.7,3947 4773.6,3906.9 v1(4760,3906.9)
  Bottom Layer w10: v1(3290,4436.9) 3345,4436.9 U7.13 3422.5,4466.9 3443,4487.4 3443,4555.8 3487.1,4599.8 3487.1,4609.8 100.nF.1 3480,4655.5 3523.5,4698.9 3523.5,4700.4 v1(3535,4711.9) ; v1(3559.9,4661.9) 3565,4666.9 3565,4676.9 v1(3610,4721.9) ; U5.13 3690,3556.9 4082.9,3556.9 4090,3564 4090,3566.9 v1(4103,3579.9) ; v1(3674.6,4632.3) 3679.1,4636.9 v1(3730,4636.9) ; v1(3745,4216.9) 3897.5,4216.9 ; v1(3972.9,4219) 3970.9,4216.9 3897.5,4216.9 ; C7.2 4060,3871.9 4115,3926.9 4240.9,3926.9 4262.9,3904.8 4272.9,3904.8 4280,3911.9 4280,3921.9 4227,3974.9 3863.7,3974.9 R40.2 3838.8,4011.9 3872.3,3978.4 4317.7,3978.4 4340.2,4001 4340.2,4032.9 4303.6,4069.5 4045,4069.5 3897.5,4216.9 ; v1(4125,3681.9) 4130,3686.9 v1(4130,3756.9) ; v1(4204.4,4586.9) 4226.5,4564.9 v1(4275,4564.9) ; 5.1.kΩ.2 4361.7,4805.3 5.1kΩ.2 ; v1(4455,3921.9) 4505,3971.9 4535,3971.9 v1(4537.5,3974.4) ; v1(4600,3696.9) 4600,3670.9 4664.1,3606.8 v1(4735,3606.8) ; v1(4650,4036.9) 4664.1,4022.9 4664.1,3947 4704.1,3906.9 v1(4760,3906.9) ; v1(4655,4151.9) 4655,4221.3 CN1.2 4655,4321.3 v1(4655,4391.9)
PIN11: U5.11 U7.11 U8.6 | length 2198.3
  Top Layer w10: U7.11 3385,4256.9 v1(3610,4256.9) ; U5.11 3585,3751.9 v1(3585,3776.9) ; v1(4285,4476.9) 4294,4485.9 4294,4538.7 4434.5,4679.3 U8.6
  Bottom Layer w10: U7.11 3451.9,4190.1 3451.9,3996 3397.5,3941.6 3397.5,3889.3 3422.4,3864.4 3497.5,3864.4 v1(3585,3776.9) ; v1(3610,4256.9) 3830,4476.9 v1(4285,4476.9)
PIN12: U5.12 U7.12 U8.7 | length 2412.2
  Top Layer w10: v1(3300,4346.9) 3297.5,4344.4 3297.5,3889.3 3322.4,3864.4 3352.5,3864.4 v1(3380,3836.9) ; v1(3480,4211.9) 3485,4206.9 v1(3605,4206.9) ; v1(3490,3696.9) v1(3555.3,3762.3) ; v1(4270,4411.9) 4308,4449.9 4308,4485.4 U8.7
  Bottom Layer w10: v1(3300,4346.9) 3355,4346.9 U7.12 3417.5,4324.4 3417.5,4274.4 v1(3480,4211.9) ; v1(3380,3836.9) 3454.7,3762.3 v1(3555.3,3762.3) ; v1(3490,3696.9) 3547.1,3639.8 3547.1,3614 U5.12 ; v1(3605,4206.9) 3605,4219.4 3797.5,4411.9 v1(4270,4411.9)
VCC: 3A.1 3B.1 100.nF.2 100n.F.1 C7.1 CN1.1 U5.10 U5.16 U7.10 U7.16 U8.8 U9.3 | length 4471
  Top Layer w10: v1(3215,4181.9) 3215,4476.9 v1(3235,4496.9) ; U7.16 3430,4766.9 100.nF.2 ; U5.16 3950,3606.9 C7.1 4151.9,3716.9 4160.8,3725.9 4319,3725.9 3B.1 3A.1 4502.4,3794.3 U9.3 4542,3829 4542,3664.9 4565,3641.9 4690,3641.9 4694.7,3646.6 4694.7,3920.5 4775,4000.8 4775,4131.9 4714.4,4192.6 CN1.1 4654.4,4192.6 100n.F.1 4450,4496.4 U8.8
  Bottom Layer w10: v1(3215,4181.9) 3360,4181.9 U7.10 3315,4106.9 3315,3992 3382.5,3924.5 3382.5,3889.3 3340,3846.8 U5.10 3465,3731.9 3775.1,3731.9 3900.1,3606.9 U5.16 ; v1(3235,4496.9) 3310,4571.9 3310,4736.9 3317.1,4744 3352.1,4744 U7.16
pads on no net: U5.9 U9.1

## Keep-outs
Board Outline Layer:
  the board outline again, w10

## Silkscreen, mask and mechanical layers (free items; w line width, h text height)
Top Silkscreen Layer:
  region: 3379 vertices and 0 holes, not listed, extent 3830,4637.7 4025,4776.9
  text "-" at 4745,4446.9 h120 r180
  text "≽^•⩊•^≼" at 4375,4251.9 h60
  text "@tengy_ez" at 3470,4136.9 h60
  text "@i.matsudzu" at 3450,4066.9 h60
  text "+" at 4675,3996.9 h120
  text "www.tengy.org" at 3015,3966.9 h54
